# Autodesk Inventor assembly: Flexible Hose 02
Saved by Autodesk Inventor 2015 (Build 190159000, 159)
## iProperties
Created: 2013-02
Part Number: Flexible Hose 02
Document SubType Name: Assembly
Designer: Marci
Name: Hydraulic Hose - No Fittings
ActiveState: True
PipeType: Flexible Hose
Material: UnInitValue
Standard: UnInitValue
FittingMaterial: UnInitValue
FittingStandard: UnInitValue
RouteDirection90: UnInitValue
RouteDirection45: UnInitValue
IsFlanged: UnInitValue
IsButtWelded: UnInitValue
DiameterType: Nominal
Diameter: 1/4
Schedule: ID=0.25
OD: 1,4986
ID: 0,635
Ending: UnInitValue
IntermediateSegmentsMin: UnInitValue
IntermediateSegmentsMax: UnInitValue
IntermediateSegmentsInc: UnInitValue
TerminationSegmentsMin: UnInitValue
TerminationSegmentsMax: UnInitValue
TerminationSegmentsInc: UnInitValue
RoundUpValue: 0.125 in
DefaultBendRadius: UnInitValue
BendRadius: 0.500 in
PipingComponentColor: Blue (Flat)
PipeKey: v3#d489867e-ac9b-47ea-b952-0a1b885f66be#1
CouplingKey: UnInitValue
Elbow90Key: UnInitValue
Elbow45Key: UnInitValue
SuppressStartFitting: True
SuppressEndFitting: True
FlangeKey: UnInitValue
GasketKey: UnInitValue
Gap: UnInitValue
UseSubASM: True
_ComponentInfo: <CS><C N="Pipe" R="0,749300" OR="0,749300" IR="0,317500" PL="PL" PartType="pipe" SymKey="" PN="Parker hidraulikatömlő - No Skive 1/4"><CO N="1"><FE V="0"/><FD V
ShowGap: UnInitValue
MixedUnits: UnInitValue
UseFlangsForCouplings: UnInitValue
IsSelfDraining: UnInitValue
ElbowCustomKey: UnInitValue
Angle: UnInitValue
Author: Marci
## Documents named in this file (3)
- C:\Users\Andrew Almeida\Documents\Projeto WS2015\WS2015 CAD Data ANLAS\01\Pneumatic System\Engine\Pneumatikus hajtás\Teljes hajtás\AIP\Tube and Pipe\Run06\Teljes hajtás.Hose02.iam
- C:\Users\Andrew Almeida\Documents\Projeto WS2015\WS2015 CAD Data ANLAS\01\Pneumatic System\Engine\Pneumatikus hajtás\Teljes hajtás\AIP\Tube and Pipe\Run06\Teljes hajtás.Hose02.ipt
- C:\Users\Andrew Almeida\Documents\Projeto WS2015\WS2015 CAD Data ANLAS\01\Pneumatic System\Engine\Pneumatikus hajtás\Teljes hajtás\AIP\Tube and Pipe\Run06\pifhose.1360342570136.ipt
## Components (2 placed, 2 different names)
1. Hose02
2. Flexible Hose:1
